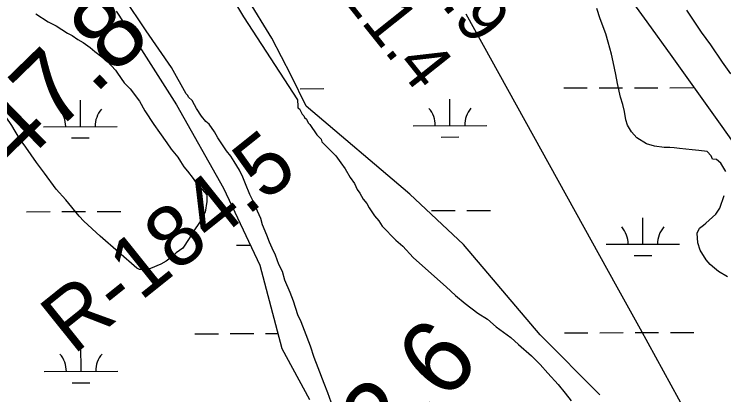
# Model space of a CAD drawing. Extents: x 3355724 to 3393621, y 594744 to 620174.
# Drawn here: x 3377127 to 3378091, y 614569 to 615086 of the extents above; entities that cross this region are included whole.
import ezdxf

# ---------------------------------------------------------------- set-up
doc = ezdxf.new("R2010")
doc.units = 0
for name, color, linetype in [('V-RIVR-EDGE', 7, 'Continuous'), ('V-RIVR-RANG', 7, 'Continuous'), ('V-RIVR-RANG-IDEN', 7, 'Continuous'), ('V-SITE-VEGE', 7, 'Continuous'), ('V-SURV-IDEN', 7, 'Continuous'), ('V-TOPO-MINR', 7, 'Continuous'), ('V-WETL-SWMP', 7, 'Continuous')]:
    doc.layers.add(name, color=color, linetype=linetype)

msp = doc.modelspace()

# ---------------------------------------------------------------- linework, layer by layer
at = {"layer": 'V-RIVR-EDGE'}
msp.add_spline([(3375380.82, 618352.84), (3375420.27, 618323.73), (3375445.07, 618301.37), (3375471.34, 618279.74), (3375501.25, 618255.17), (3375536.28, 618227.67), (3375549.03, 618211.92), (3375559.98, 618204.95), (3375576.4, 618194.3), (3375599.75, 618175.24), (3375638.78, 618140.78), (3375656.28, 618122.46), (3375673.42, 618104.87), (3375771.52, 618011.41), (3375800.34, 617985.75), (3375821.85, 617963.4), (3375844.09, 617941.05), (3375861.61, 617929.67), (3375882.4, 617909.52), (3375904.26, 617880.22), (3375960.43, 617832.56), (3375992.15, 617799.58), (3376041.01, 617748.28), (3376074.55, 617712.01), (3376185.41, 617603.17), (3376226.98, 617561.76), (3376338.57, 617455.84), (3376381.97, 617411.87), (3376437.4, 617359.09), (3376479.69, 617314.75), (3376500.1, 617289.48), (3376531.46, 617257.97), (3376571.57, 617217.29), (3376620.05, 617160.14), (3376637.9, 617137.07), (3376661.24, 617115.08), (3376679.48, 617098.95), (3376697.71, 617079.53), (3376717.03, 617058.28), (3376731.6, 617036.68), (3376745.46, 617023.12), (3376758.95, 617009.2), (3376794.67, 616969.63), (3376867.2, 616883.18), (3376881.79, 616866.69), (3376901.83, 616843.98), (3376931.38, 616817.22), (3376968.56, 616773.26), (3377038.17, 616690.11), (3377066.96, 616652.75), (3377087.74, 616632.96), (3377103.06, 616618.67), (3377120.92, 616596.33), (3377186.51, 616512.45), (3377216.03, 616475.46), (3377255.39, 616427.84), (3377303.85, 616366.31), (3377369.46, 616288.29), (3377405.91, 616245.79), (3377491.52, 616128.6), (3377526.12, 616075.88), (3377552.72, 616041.09), (3377626.7, 615950.25), (3377654.4, 615916.18), (3377678.45, 615886.15), (3377699.95, 615857.22), (3377777.92, 615752.48), (3377803.06, 615722.81), (3377843.53, 615678.11), (3377867.95, 615650.27), (3377881.43, 615631.96), (3377905.48, 615598.27), (3377926.6, 615565.68), (3377940.8, 615543.35), (3377958.65, 615518.81), (3377971.76, 615499.4), (3377982.68, 615481.47), (3378059.55, 615375.27), (3378094.52, 615325.1), (3378126.94, 615277.13), (3378185.17, 615175.73), (3378207.01, 615135.1), (3378307.9, 614987.17), (3378349.41, 614923.1), (3378390.94, 614864.14), (3378419.72, 614826.42), (3378449.24, 614789.42), (3378467.07, 614756.12), (3378482.35, 614726.47), (3378509.65, 614679.24), (3378546.06, 614621.03), (3378577.36, 614566.49), (3378597.73, 614524.77), (3378622.46, 614473.89), (3378650.12, 614424.48), (3378694.9, 614351.25), (3378714.91, 614311), (3378749.11, 614248.04), (3378759.68, 614232.66), (3378776.79, 614205.93), (3378791.7, 614172.99), (3378807.69, 614137.86), (3378844.81, 614066.85), (3378863.71, 614025.13), (3378885.92, 613990.72), (3378900.11, 613964), (3378916.5, 613936.54), (3378929.25, 613918.23), (3379005.71, 613794.85), (3379023.17, 613762.64), (3379028.99, 613751.66), (3379038.1, 613737.75), (3379055.97, 613721.98), (3379063.26, 613712.46), (3379072.71, 613690.14), (3379096.69, 613633.42), (3379107.6, 613608.17), (3379127.6, 613568.28), (3379150.17, 613527.28), (3379171.28, 613493.23), (3379216.04, 613409.41), (3379256.8, 613334.37), (3379314.98, 613211.4), (3379346.24, 613141.14), (3379363.68, 613098.33), (3379415.72, 613001.69), (3379435.35, 612957.78), (3379449.52, 612923.75), (3379470.62, 612881.66), (3379540.48, 612750.98), (3379564.86, 612706.33), (3379589.61, 612660.57), (3379652.22, 612553.68), (3379662.4, 612530.99), (3379662.74, 612523.68), (3379672.94, 612508.3), (3379687.86, 612480.85), (3379704.23, 612446.81), (3379704.94, 612442.05), (3379706.03, 612437.3), (3379717.66, 612409.12), (3379731.49, 612386.43), (3379735.12, 612376.91), (3379746.04, 612354.95), (3379762.07, 612334.44), (3379789.38, 612291.97), (3379802.84, 612266.35), (3379843.96, 612191.31), (3379872.71, 612135.68), (3379896.37, 612098.33), (3379901.45, 612082.97), (3379906.5, 612054.81), (3379909.41, 612046.76), (3379918.88, 612032.84), (3379935.28, 612013.06), (3379944.73, 611991.47), (3379953.43, 611964.03), (3379958.89, 611953.42), (3379967.28, 611946.09), (3379978.56, 611926.69), (3379993.48, 611899.96), (3380009.51, 611874.34), (3380070.27, 611759.4), (3380080.8, 611731.23), (3380088.07, 611713.3), (3380095.7, 611697.56), (3380112.46, 611674.13), (3380124.83, 611651.8), (3380123.72, 611645.22), (3380124.79, 611635.35), (3380137.16, 611610.46), (3380148.81, 611592.52), (3380155.02, 611587.75), (3380167.04, 611570.54), (3380177.58, 611546.39), (3380195.78, 611514.17), (3380214.71, 611483.42), (3380224.53, 611465.85), (3380228.15, 611449.39), (3380233.59, 611432.56), (3380253.97, 611395.96), (3380276.52, 611349.11), (3380293.96, 611306.3), (3380320.89, 611258.71), (3380341.28, 611224.67), (3380352.57, 611207.46), (3380364.6, 611196.1), (3380367.14, 611187.68), (3380368.95, 611179.64), (3380378.42, 611166.45), (3380389, 611155.46), (3380388.98, 611149.98), (3380391.14, 611136.81), (3380399.14, 611120.71), (3380419.9, 611089.58), (3380436.68, 611073.46), (3380444.33, 611062.84), (3380443.95, 611058.82), (3380442.84, 611052.97), (3380446.48, 611044.92), (3380459.96, 611025.88), (3380464.31, 611010.88), (3380471.21, 610992.22), (3380486.47, 610958.19), (3380519.26, 610912.78), (3380526.88, 610891.19), (3380537.4, 610858.27), (3380551.57, 610822.77), (3380593.77, 610740.06), (3380615.24, 610699.43), (3380640.74, 610663.54), (3380652.38, 610642.31), (3380663.65, 610615.23), (3380668, 610601.33), (3380674.19, 610590.71), (3380692.06, 610574.95), (3380702.63, 610562.49), (3380712.46, 610543.83), (3380727.72, 610509.79), (3380735.35, 610487.84), (3380741.14, 610466.26), (3380745.88, 610461.13), (3380752.82, 610456.36), (3380760.47, 610445.74), (3380779.75, 610409.14), (3380795.75, 610376.2), (3380801.59, 610370.34), (3380807.42, 610366.3), (3380811.79, 610355.69), (3380812.49, 610344.36), (3380817.94, 610330.45), (3380829.23, 610313.24), (3380839.05, 610293.84), (3380846.35, 610289.44), (3380854.01, 610282.84), (3380859.1, 610273.69), (3380867.1, 610253.93), (3380868.55, 610249.54), (3380877.66, 610239.65), (3380887.13, 610223.91), (3380896.59, 610208.53), (3380899.85, 610194.27), (3380899.84, 610190.24), (3380906.05, 610188.77), (3380912.99, 610185.09), (3380918.45, 610177.04), (3380918.43, 610171.19), (3380918.42, 610164.61), (3380918.4, 610157.66), (3380926.06, 610151.8), (3380935.54, 610140.81), (3380947.18, 610118.84), (3380956.29, 610103.83), (3380965.04, 610094.67), (3380973.4, 610078.94), (3380975.21, 610070.16), (3380981.77, 610062.1), (3380992.71, 610052.93), (3380996.72, 610044.88), (3380999.97, 610032.08), (3380999.95, 610022.94), (3381003.22, 610013.06), (3381010.15, 610006.83), (3381018.91, 610001.33), (3381025.83, 609991.44), (3381035.3, 609976.79), (3381052.05, 609952.26), (3381064.06, 609932.49), (3381081.17, 609901.74), (3381081.14, 609891.87), (3381086.58, 609872.85), (3381093.84, 609850.9), (3381104.02, 609830.4), (3381125.49, 609791.6), (3381152.44, 609750.23), (3381171.02, 609723.86), (3381189.57, 609687.99), (3381212.13, 609645.9), (3381231.43, 609613.32), (3381244.14, 609581.49), (3381257.94, 609543.07), (3381275.04, 609509.4), (3381303.06, 609460.34), (3381339.81, 609389.7), (3381375.86, 609334.05), (3381398.43, 609297.8), (3381410.81, 609276.57), (3381420.3, 609271.8), (3381423.22, 609268.13), (3381426.13, 609261.55), (3381429.78, 609259.34), (3381434.89, 609258.6), (3381439.64, 609256.39), (3381499.34, 609155.72), (3381528.08, 609097.89), (3381535.35, 609085.08), (3381535.33, 609077.04), (3381535.31, 609065.34), (3381535.29, 609058.03), (3381541.13, 609053.63), (3381551.71, 609048.49), (3381554.98, 609039.7), (3381564.07, 609020.67), (3381586.27, 608978.95), (3381604.83, 608944.17), (3381620.11, 608915.26), (3381628.49, 608903.54), (3381636.88, 608898.4), (3381651.08, 608874.6), (3381663.08, 608850.81), (3381678.38, 608829.21), (3381690.77, 608814.56), (3381704.61, 608790.4), (3381708.22, 608774.67), (3381710.37, 608757.85), (3381710.35, 608748.71), (3381708.5, 608737.75), (3381708.12, 608732.26), (3381711.37, 608718), (3381715.71, 608697.15), (3381717.88, 608689.84), (3381723.34, 608678.49), (3381733.53, 608661.65), (3381741.56, 608656.51), (3381747.03, 608652.48), (3381752.87, 608648.08), (3381759.82, 608648.06), (3381763.47, 608646.95), (3381765.65, 608640.74), (3381769.29, 608633.42), (3381776.21, 608626.45), (3381784.62, 608624.97), (3381791.56, 608623.86), (3381802.13, 608612.86), (3381808.33, 608607.36), (3381820.72, 608590.88), (3381831.67, 608582.82), (3381840.78, 608572.56), (3381857.51, 608537.79), (3381870.22, 608504.13), (3381876.02, 608481.45), (3381884.75, 608464.98), (3381898.59, 608444.11), (3381913.54, 608430.18), (3381932.09, 608392.48), (3381960.83, 608337.21), (3381973.56, 608310.86), (3381973.55, 608307.21), (3381972.8, 608299.9), (3381972.79, 608295.14), (3381974.97, 608287.83), (3381977.88, 608282.34), (3381985.91, 608277.2), (3381990.28, 608270.98), (3381997.19, 608259.26), (3382005.93, 608242.42), (3382015.74, 608221.2), (3382031.03, 608193.01), (3382044.49, 608168.85), (3382063.05, 608134.08), (3382080.13, 608094.92), (3382096.49, 608059.06), (3382116.86, 608016.61), (3382135.05, 607983.3), (3382154.33, 607945.23), (3382180.52, 607889.97), (3382186.33, 607875.7), (3382201.59, 607836.91), (3382211, 607801.06), (3382218.99, 607778.02), (3382226.27, 607767.03), (3382233.56, 607756.78), (3382247.73, 607722.75), (3382259, 607698.23), (3382261.54, 607688.35), (3382266.62, 607674.81), (3382271, 607670.42), (3382277.91, 607659.43), (3382286.29, 607646.25), (3382288.82, 607636.74), (3382293.54, 607621.01), (3382300.43, 607600.89), (3382310.61, 607578.93), (3382319.72, 607565.75), (3382337.93, 607536.82), (3382350.3, 607516.32), (3382357.57, 607499.12), (3382366.3, 607481.92), (3382374.32, 607469.47), (3382380.88, 607463.97), (3382386.73, 607463.23), (3382390.75, 607463.22), (3382394.4, 607459.92), (3382404.95, 607439.06), (3382412.58, 607420.03), (3382419.09, 607395.52), (3382431.81, 607365.52), (3382444.54, 607336.97), (3382461.28, 607305.86), (3382481.64, 607263.77), (3382528.25, 607190.18), (3382546.82, 607161.62), (3382558.1, 607140.03), (3382565.37, 607121.36), (3382577.74, 607099.04), (3382593.75, 607069.75), (3382609.41, 607044.12), (3382624.34, 607021.42), (3382632.36, 607011.17), (3382645.48, 606997.98), (3382659.35, 606986.98), (3382671.37, 606972.69), (3382685.21, 606951.82)], degree=3, dxfattribs=at)
at = {"layer": 'V-SITE-VEGE'}
for p, q in [((3377397.54, 615152.04), (3377438.36, 615082.62)), ((3377306.12, 615063.71), (3377270.97, 615116.45)), ((3377438.36, 615082.62), (3377511.48, 614970.21)), ((3377340.55, 615013.77), (3377306.12, 615063.71)), ((3377360.27, 614978.36), (3377340.55, 615013.77)), ((3377362.61, 614975.99), (3377360.27, 614978.36)), ((3377363.78, 614973.64), (3377362.61, 614975.99)), ((3377368.46, 614968.91), (3377363.78, 614973.64)), ((3377371.97, 614963.01), (3377368.46, 614968.91)), ((3377511.48, 614970.21), (3377511.99, 614961.24)), ((3377374.3, 614958.29), (3377371.97, 614963.01)), ((3377381.32, 614947.68), (3377374.3, 614958.29)), ((3377511.99, 614961.24), (3377511.98, 614958.89)), ((3377511.98, 614958.89), (3377514.33, 614957.7)), ((3377514.33, 614957.7), (3377517.83, 614950.63)), ((3377387.17, 614940.59), (3377381.32, 614947.68)), ((3377517.83, 614950.63), (3377520.17, 614948.27)), ((3377520.17, 614948.27), (3377521.34, 614945.91)), ((3377391.87, 614937.04), (3377387.17, 614940.59)), ((3377521.34, 614945.91), (3377523.68, 614943.54)), ((3377523.68, 614943.54), (3377526.02, 614938.83)), ((3377526.02, 614938.83), (3377528.36, 614936.46)), ((3377398.88, 614926.42), (3377391.87, 614937.04)), ((3377528.36, 614936.46), (3377537.71, 614922.3)), ((3377403.55, 614918.16), (3377398.88, 614926.42)), ((3377415.25, 614900.47), (3377403.55, 614918.16)), ((3377537.71, 614922.3), (3377543.57, 614916.4)), ((3377543.57, 614916.4), (3377544.73, 614912.86)), ((3377544.73, 614912.86), (3377563.48, 614893.96)), ((3377421.1, 614893.38), (3377415.25, 614900.47)), ((3377425.78, 614886.3), (3377421.1, 614893.38)), ((3377563.48, 614893.96), (3377570.5, 614884.51)), ((3377432.79, 614874.5), (3377425.78, 614886.3)), ((3377570.5, 614884.51), (3377576.35, 614876.25)), ((3377437.45, 614865.07), (3377432.79, 614874.5)), ((3377576.35, 614876.25), (3377583.36, 614864.45)), ((3377440.94, 614855.64), (3377437.45, 614865.07)), ((3377583.36, 614864.45), (3377589.21, 614856.19)), ((3377446.77, 614841.5), (3377440.94, 614855.64)), ((3377589.21, 614856.19), (3377592.7, 614847.94)), ((3377451.43, 614832.06), (3377446.77, 614841.5)), ((3377592.7, 614847.94), (3377596.21, 614843.22)), ((3377596.21, 614843.22), (3377600.89, 614834.96)), ((3377454.93, 614823.81), (3377451.43, 614832.06)), ((3377600.89, 614834.96), (3377605.57, 614829.06)), ((3377461.93, 614808.48), (3377454.93, 614823.81)), ((3377605.57, 614829.06), (3377609.07, 614823.16)), ((3377609.07, 614823.16), (3377616.09, 614812.54)), ((3377616.09, 614812.54), (3377621.94, 614805.46)), ((3377464.24, 614800.24), (3377461.93, 614808.48)), ((3377621.94, 614805.46), (3377626.62, 614798.38)), ((3377470.07, 614786.09), (3377464.24, 614800.24)), ((3377626.62, 614798.38), (3377645.37, 614779.47)), ((3377473.56, 614776.66), (3377470.07, 614786.09)), ((3377477.05, 614768.41), (3377473.56, 614776.66)), ((3377645.37, 614779.47), (3377654.75, 614771.2)), ((3377481.72, 614758.98), (3377477.05, 614768.41)), ((3377654.75, 614771.2), (3377668.8, 614755.84)), ((3377486.37, 614746.02), (3377481.72, 614758.98)), ((3377668.8, 614755.84), (3377693.42, 614733.38)), ((3377491.04, 614736.58), (3377486.37, 614746.02)), ((3377494.52, 614724.8), (3377491.04, 614736.58)), ((3377693.42, 614733.38), (3377713.35, 614715.64)), ((3377501.51, 614708.3), (3377494.52, 614724.8)), ((3377713.35, 614715.64), (3377726.24, 614703.82)), ((3377506.17, 614696.51), (3377501.51, 614708.3)), ((3377511.97, 614677.66), (3377506.17, 614696.51)), ((3377726.24, 614703.82), (3377739.14, 614693.18)), ((3377739.14, 614693.18), (3377756.74, 614680.16)), ((3377516.64, 614668.23), (3377511.97, 614677.66)), ((3377756.74, 614680.16), (3377769.64, 614671.87)), ((3377521.3, 614656.44), (3377516.64, 614668.23)), ((3377769.64, 614671.87), (3377781.37, 614661.23)), ((3377781.37, 614661.23), (3377801.31, 614647.02)), ((3377529.44, 614635.22), (3377521.3, 614656.44)), ((3377801.31, 614647.02), (3377811.86, 614637.57)), ((3377534.08, 614619.91), (3377529.44, 614635.22)), ((3377811.86, 614637.57), (3377829.45, 614622.2)), ((3377539.91, 614605.76), (3377534.08, 614619.91)), ((3377829.45, 614622.2), (3377841.16, 614610.38)), ((3377841.16, 614610.38), (3377851.7, 614598.57)), ((3377548.06, 614584.55), (3377539.91, 614605.76)), ((3377851.7, 614598.57), (3377865.76, 614583.21)), ((3377552.71, 614571.59), (3377548.06, 614584.55)), ((3377865.76, 614583.21), (3377875.12, 614571.4)), ((3377559.69, 614552.73), (3377552.71, 614571.59)), ((3377875.12, 614571.4), (3377883.31, 614560.78))]:
    msp.add_line(p, q, dxfattribs=at)
for points in [[(3377296.85, 614739.19), (3377293.48, 614741.4), (3377243.54, 614784.64), (3377221.65, 614805.16), (3377214.91, 614811.82), (3377196.92, 614834.04), (3377183.99, 614848.47), (3377168.23, 614870.15), (3377156.98, 614884.6), (3377142.89, 614905.73), (3377133.89, 614917.39), (3377123.74, 614935.2), (3377115.86, 614946.31), (3377105.15, 614962.44), (3377097.84, 614971.88), (3377087.15, 614986.33), (3377084.34, 614989.11), (3376987.1, 615099.61)], [(3378093.19, 614872.36), (3378086.42, 614884.04), (3378080.81, 614889.03), (3378075.22, 614889.56), (3378073.52, 614894.01), (3378067.9, 614899.56), (3378056.73, 614901.17), (3378047.79, 614902.23), (3378030.48, 614903.8), (3378023.21, 614904.87), (3378017.07, 614905.4), (3378009.81, 614905.35), (3377996.41, 614906.95), (3377985.78, 614910.23), (3377972.33, 614918.53), (3377965.03, 614926.3), (3377959.95, 614935.76), (3377957.67, 614943), (3377955.93, 614954.15), (3377953.64, 614963.63), (3377950.23, 614973.66), (3377946.21, 614992.05), (3377943.91, 615004.32), (3377940.45, 615021.6), (3377938.16, 615032.2), (3377933.59, 615048.36), (3377930.18, 615059.5), (3377922.8, 615080.11), (3377918.25, 615094.04)], [(3378039.95, 615091.98), (3378059.67, 615061.95), (3378072.61, 615044.73), (3378088.38, 615021.38), (3378099.64, 615005.26)], [(3377156.32, 615086.67), (3377173.13, 615076.16), (3377183.77, 615070.65), (3377199.46, 615060.69), (3377205.62, 615057.38), (3377213.47, 615051.84), (3377220.75, 615047.98), (3377230.28, 615041.34), (3377236.45, 615035.79), (3377245.99, 615028.59), (3377253.28, 615022.5), (3377264.52, 615010.29), (3377267.33, 615006.39), (3377276.34, 614993.05), (3377284.21, 614984.73), (3377297.15, 614968.06), (3377304.48, 614955.26), (3377316.32, 614936.35), (3377324.2, 614925.79), (3377334.33, 614911.34), (3377339.96, 614903), (3377348.96, 614891.89), (3377352.9, 614886.33), (3377357.41, 614879.1), (3377362.47, 614872.99), (3377369.79, 614862.99), (3377374.29, 614856.32), (3377378.79, 614851.88), (3377388.34, 614840.77), (3377388.4, 614831.84), (3377386.25, 614817.31), (3377380.18, 614806.11), (3377369.12, 614789.3), (3377364.7, 614781.46), (3377355.85, 614768.57), (3377346.95, 614761.81), (3377342.51, 614757.32), (3377333.06, 614750.57), (3377325.83, 614746.61), (3377311.91, 614740.95), (3377302.99, 614739.22), (3377296.85, 614739.19)], [(3378095.72, 614729.47), (3378083.4, 614736.65), (3378077.79, 614741.08), (3378072.18, 614746.08), (3378066.55, 614752.74), (3378058.66, 614765.53), (3378055.25, 614775.56), (3378054.61, 614788.95), (3378057.36, 614795.67), (3378062.92, 614799.61), (3378066.25, 614802.42), (3378079.58, 614814.78), (3378085.11, 614822.63), (3378091.15, 614839.97)]]:
    msp.add_lwpolyline(points, dxfattribs=at)
at = {"layer": 'V-TOPO-MINR'}
for points in [[(3378337.73, 614581.37), (3378088.18, 614933.85), (3378054.45, 614981.33), (3378020.61, 615028.73), (3377986.63, 615076.03), (3377952.54, 615123.26)], [(3377740.38, 615086.75), (3377945.52, 614715.94), (3377976.94, 614658.88), (3378008.22, 614601.74), (3378039.26, 614544.48), (3378070.16, 614487.14), (3378111.09, 614410.82)]]:
    msp.add_lwpolyline(points, dxfattribs=at)
at = {"layer": 'V-WETL-SWMP'}
for p, q in [((3377476.81, 615053.95), (3377436.01, 615120.58)), ((3377265.52, 615090.3), (3377296.46, 615043.11)), ((3377502.89, 615003.25), (3377476.81, 615053.95)), ((3377296.46, 615043.11), (3377347.09, 614963.31)), ((3377523.34, 614961.58), (3377502.89, 615003.25)), ((3377873.2, 614986.07), (3377905.2, 614986.15)), ((3377921.2, 614986.19), (3377953.2, 614986.28)), ((3377969.2, 614986.32), (3378001.2, 614986.4)), ((3378017.2, 614986.44), (3378049.2, 614986.53)), ((3377515.29, 614985.13), (3377547.29, 614985.21)), ((3377216.83, 614933.61), (3377216.74, 614969.61)), ((3377718.74, 614934.92), (3377718.64, 614970.92)), ((3377347.09, 614963.31), (3377411.33, 614850.07)), ((3377664.29, 614841.95), (3377523.34, 614961.58)), ((3377166.83, 614933.48), (3377266.83, 614933.74)), ((3377668.74, 614934.79), (3377768.74, 614935.05)), ((3377204.87, 614918.14), (3377228.87, 614918.21)), ((3377706.78, 614919.46), (3377730.78, 614919.52)), ((3377411.33, 614850.07), (3377460.31, 614745.14)), ((3377736.96, 614773.39), (3377664.29, 614841.95)), ((3377143.73, 614817.98), (3377175.73, 614818.07)), ((3377191.73, 614818.11), (3377223.72, 614818.19)), ((3377239.72, 614818.23), (3377271.72, 614818.32)), ((3377693.63, 614819.42), (3377725.63, 614819.51)), ((3377741.63, 614819.55), (3377773.63, 614819.63)), ((3377980.6, 614773.74), (3377980.5, 614809.74)), ((3377841.17, 614650.58), (3377736.96, 614773.39)), ((3377930.6, 614773.61), (3378030.6, 614773.87)), ((3377428.69, 614772.3), (3377447.61, 614772.35)), ((3377968.64, 614758.28), (3377992.64, 614758.34)), ((3377460.31, 614745.14), (3377490.43, 614632.05)), ((3377372.16, 614652.08), (3377404.16, 614652.16)), ((3377420.16, 614652.2), (3377452.16, 614652.29)), ((3377468.16, 614652.33), (3377485.02, 614652.37)), ((3377922.01, 614569.04), (3377841.17, 614650.58)), ((3377874.07, 614653.39), (3377906.07, 614653.48)), ((3377922.07, 614653.52), (3377954.07, 614653.6)), ((3377970.07, 614653.64), (3378002.07, 614653.73)), ((3378018.07, 614653.77), (3378050.07, 614653.85)), ((3377217.7, 614600.93), (3377217.61, 614636.93)), ((3377490.43, 614632.05), (3377527.79, 614562.47)), ((3377167.7, 614600.8), (3377267.7, 614601.06)), ((3377205.74, 614585.47), (3377229.74, 614585.53))]:
    msp.add_line(p, q, dxfattribs=at)
for centre, start, end in [((3377161.59, 614933.94), 359.37818, 40.92184), ((3377272.07, 614934.23), 139.37818, 180.92184), ((3377663.49, 614935.25), 359.37818, 40.92184), ((3377773.98, 614935.54), 139.37818, 180.92184), ((3377925.35, 614774.07), 359.37818, 40.92184), ((3378035.84, 614774.36), 139.37818, 180.92184), ((3377162.46, 614601.26), 359.37818, 40.92184), ((3377272.94, 614601.55), 139.37818, 180.92184)]:
    msp.add_arc(centre, 35.25, start, end, dxfattribs=at)

# ---------------------------------------------------------------- texts
at = {"layer": 'V-RIVR-RANG'}
for s, p in [('20.9', (3377643.68, 615177.4)), ('21.4', (3377565.81, 615114.66))]:
    msp.add_text(s, height=67, rotation=308.56833, dxfattribs=at).set_placement(p)
at = {"layer": 'V-RIVR-RANG-IDEN'}
msp.add_text('R-184.5', height=83, rotation=38.70632, dxfattribs=at).set_placement((3377207.23, 614622.27))
at = {"layer": 'V-SURV-IDEN'}
for s, rotation, p in [('5738+47.8', 44.23, (3376860.23, 614610.11)), ('5745+52.6', 46.17861, (3377321.63, 614152.97))]:
    msp.add_text(s, height=100, rotation=rotation, dxfattribs=at).set_placement(p)

doc.saveas('drawing.dxf')
